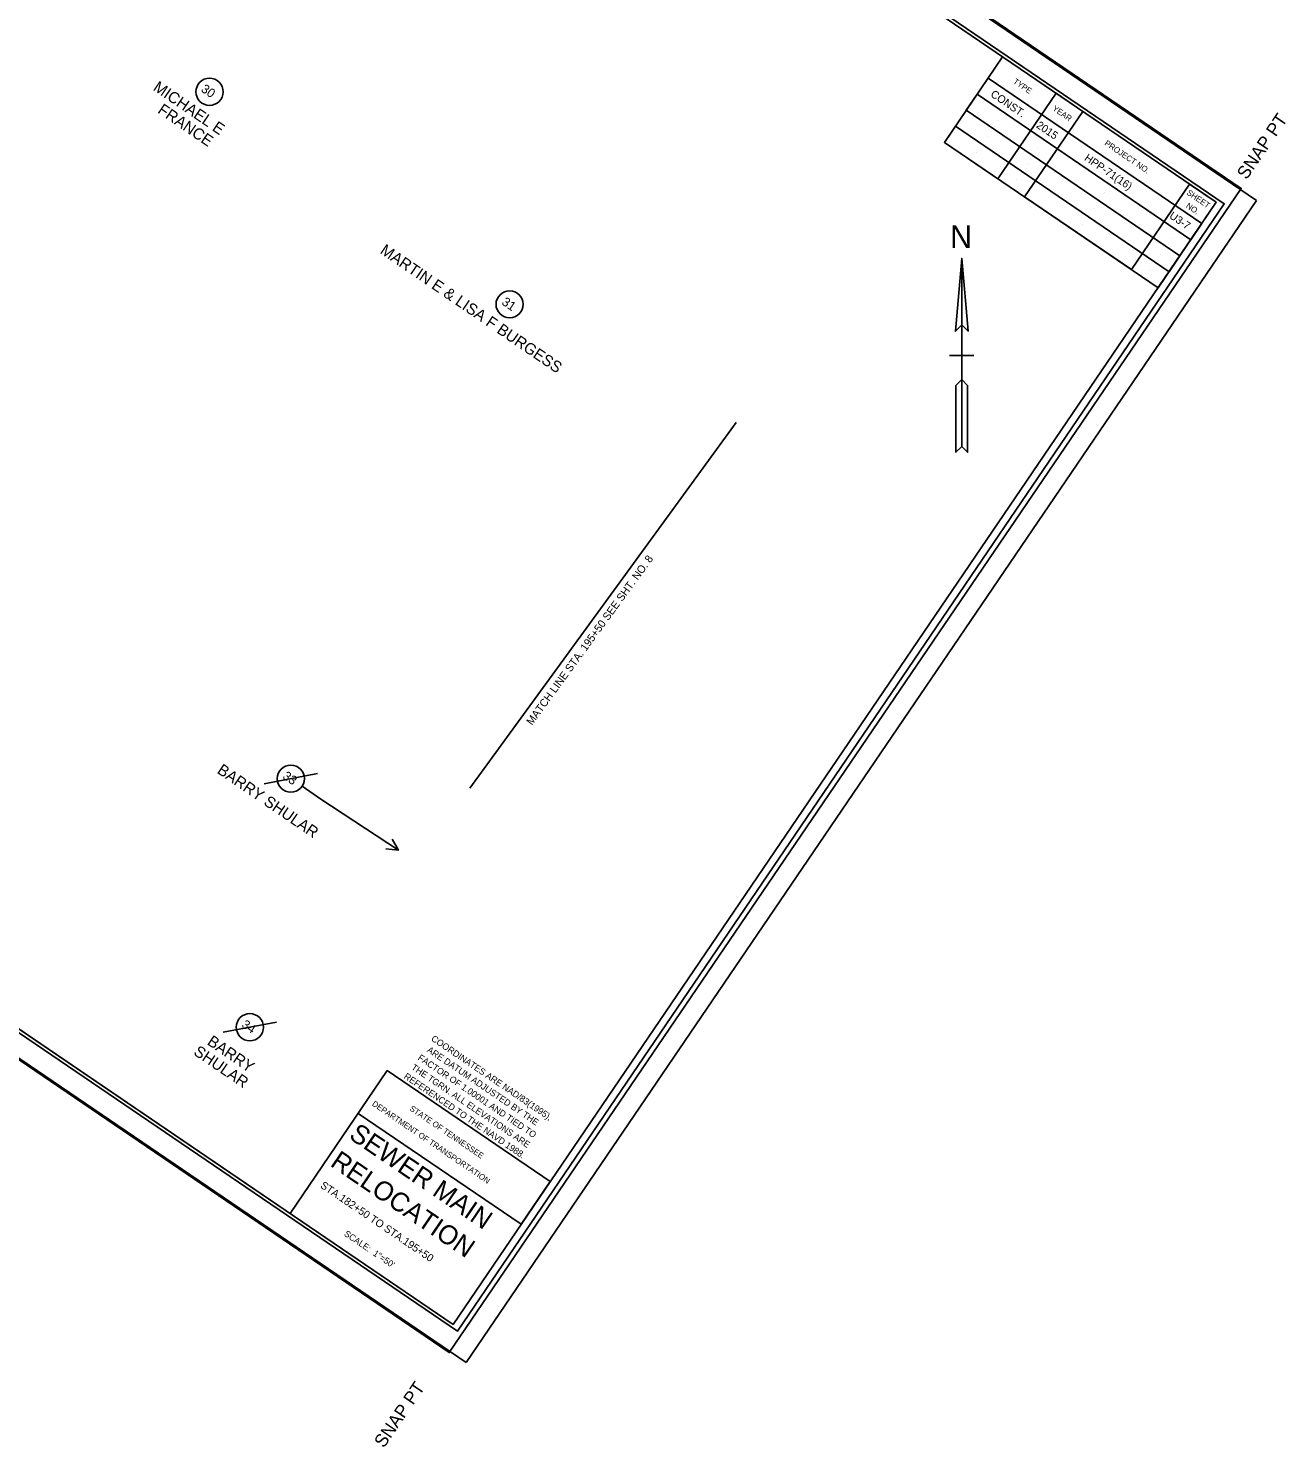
# Model space of a CAD drawing. Extents: x 2629906 to 2632029, y 567681 to 569670.
# Drawn here: x 2631056 to 2632029, y 567681 to 568779 of the extents above; entities that cross this region are included whole.
import ezdxf

# ---------------------------------------------------------------- set-up
doc = ezdxf.new("R2010")
doc.units = 0
for name, color, linetype in [('DESIGN - CENTERLINE - Proposed Text', 7, 'Continuous'), ('DESIGN - SCRATCH - User 1', 7, 'Continuous'), ('DESIGN - SHEET - Corner Text', 7, 'Continuous'), ('DESIGN - SHEET - Light Grid', 7, 'Continuous'), ('DESIGN - SHEET - Linework', 7, 'Continuous'), ('DESIGN - SHEET - Plot Shape', 7, 'Continuous'), ('SURVEY - PROPERTY - Owners', 7, 'Continuous'), ('SURVEY - PROPERTY - Tract Numbers', 7, 'Continuous')]:
    doc.layers.add(name, color=color, linetype=linetype)

msp = doc.modelspace()

# ---------------------------------------------------------------- linework, layer by layer
at = {"layer": 'DESIGN - CENTERLINE - Proposed Text'}
for p, q in [((2631778.1, 568525.9), (2631768.7, 568525.9)), ((2631787.6, 568525.9), (2631778.1, 568525.9))]:
    msp.add_line(p, q, dxfattribs=at)
for points in [[(2631778.1, 568600.9), (2631773.2, 568544.6), (2631778.1, 568549.5), (2631783, 568544.6), (2631778.1, 568600.9), (2631778.1, 568455.4), (2631782.7, 568450.9), (2631782.7, 568502.6), (2631778.1, 568507.2), (2631773.6, 568502.6), (2631773.6, 568450.9), (2631778.1, 568455.4)], [(2631397.5, 568191.1), (2631500.6, 568332.6), (2631603.6, 568474)]]:
    msp.add_lwpolyline(points, dxfattribs=at)
for points in [[(2631778.1, 568549.5), (2631783, 568544.6), (2631778.1, 568600.9)], [(2631773.6, 568450.9), (2631778.1, 568455.4), (2631778.1, 568507.2), (2631773.6, 568502.6)]]:
    msp.add_lwpolyline(points, close=True, dxfattribs=at)
at = {"layer": 'DESIGN - SCRATCH - User 1'}
for p, q in [((2631815, 568720.1), (2631815, 568720.1)), ((2631806.5, 568707.7), (2631806.5, 568707.7)), ((2631845.6, 568699.2), (2631845.6, 568699.2)), ((2631798.1, 568695.2), (2631798.1, 568695.2)), ((2631837.1, 568686.8), (2631837.1, 568686.8)), ((2631789.7, 568682.8), (2631789.7, 568682.8)), ((2631828.7, 568674.4), (2631828.7, 568674.4)), ((2631897.2, 568664.1), (2631897.2, 568664.1)), ((2631820.3, 568662), (2631820.3, 568662)), ((2631888.8, 568651.7), (2631888.8, 568651.7)), ((2631880.4, 568639.3), (2631880.4, 568639.3)), ((2631871.9, 568626.9), (2631871.9, 568626.9)), ((2631948.9, 568628.9), (2631948.9, 568628.9)), ((2631940.5, 568616.5), (2631940.5, 568616.5)), ((2631932, 568604.1), (2631932, 568604.1)), ((2631923.6, 568591.7), (2631923.6, 568591.7)), ((2631494.5, 568336.4), (2631494.5, 568336.4)), ((2631347.8, 567857.8), (2631347.8, 567857.8))]:
    msp.add_line(p, q, dxfattribs=at)
at = {"layer": 'DESIGN - SHEET - Light Grid'}
msp.add_lwpolyline([(2630011.2, 568707.4), (2631387.9, 567770.9), (2631981.3, 568643.2), (2630604.6, 569579.7)], close=True, dxfattribs=at)
at = {"layer": 'DESIGN - SHEET - Linework'}
for p, q in [((2630518, 569658.2), (2632006.3, 568645.8)), ((2629906.4, 568759.1), (2631394.7, 567746.7)), ((2632006.3, 568645.8), (2631394.7, 567746.7))]:
    msp.add_line(p, q, dxfattribs=at)
for points in [[(2630673.6, 569529.8), (2630083, 568661.6), (2631384.6, 567776.2), (2631975.1, 568644.4), (2630673.6, 569529.8)], [(2631809.8, 568756.9), (2631764.8, 568690.7), (2631930.1, 568578.2), (2631975.1, 568644.4), (2631954.5, 568658.4), (2631909.5, 568592.3), (2631826.8, 568648.5), (2631871.8, 568714.7), (2631851.1, 568728.7), (2631806.1, 568662.6), (2631764.8, 568690.7), (2631773.2, 568703.1), (2631938.6, 568590.6), (2631947, 568603), (2631781.6, 568715.5), (2631790.1, 568727.9), (2631955.5, 568615.4), (2631963.9, 568627.8), (2631798.5, 568740.3)], [(2631258.5, 567862), (2631333.6, 567972.5), (2631459.7, 567886.7), (2631437.2, 567853.6), (2631311.1, 567939.4)]]:
    msp.add_lwpolyline(points, dxfattribs=at)
at = {"layer": 'DESIGN - SHEET - Plot Shape'}
for points in [[(2630588.8, 569611.3), (2631994.4, 568655.1), (2631381.6, 567754.4), (2629976, 568710.6)], [(2630603.2, 569577.6), (2631975.1, 568644.4), (2631384.6, 567776.2), (2630012.6, 568709.5)]]:
    msp.add_lwpolyline(points, close=True, dxfattribs=at)
at = {"layer": 'SURVEY - PROPERTY - Tract Numbers'}
for p, q in [((2631238.4, 568194.5), (2631279.6, 568202.3)), ((2631206.6, 568002.2), (2631247.9, 568010.1))]:
    msp.add_line(p, q, dxfattribs=at)
for points in [[(2631282.2, 568182.6), (2631267.7, 568192.5)], [(2631342.3, 568143.1), (2631282.2, 568182.6)], [(2631337.4, 568151.5), (2631342.3, 568143.1), (2631332.6, 568144.2)]]:
    msp.add_lwpolyline(points, dxfattribs=at)
for centre in [(2631196.1, 568729.8), (2631428.3, 568565.4), (2631259, 568198.4), (2631227.3, 568006.1)]:
    msp.add_circle(centre, 10.5, dxfattribs=at)

# ---------------------------------------------------------------- texts
at = {"layer": 'DESIGN - CENTERLINE - Proposed Text'}
msp.add_text('N', height=17.7, dxfattribs=at).set_placement((2631769.1, 568608.9))
msp.add_text('MATCH LINE STA. 195+50 SEE SHT. NO. 8', height=6, rotation=53.918, dxfattribs=at).set_placement((2631445.6, 568239.3))
at = {"layer": 'DESIGN - SHEET - Corner Text'}
for s, height, rotation, p in [('TYPE', 4.5, 325.7738, (2631817.5, 568736.8)), ('CONST.', 6, 325.7738, (2631799.9, 568726.7)), ('YEAR', 4.5, 325.7738, (2631847.9, 568715.9)), ('  SNAP PT', 10, 55.7738, (2631994.4, 568655.1)), ('2015', 6, 325.7738, (2631835.3, 568702.6)), ('PROJECT NO.', 4.5, 325.7738, (2631888.2, 568689)), ('HPP-71(16)', 6, 325.7738, (2631872.5, 568677.3)), ('SHEET', 4.5, 325.7738, (2631951.8, 568650.7)), ('NO.', 4.5, 325.7738, (2631951.2, 568640.6)), ('U3-7', 6, 325.7738, (2631938.2, 568632.6)), ('COORDINATES ARE NAD/83(1995),', 5, 325.7738, (2631367.1, 567996.1)), ('FACTOR OF 1.00001 AND TIED TO', 5, 325.7738, (2631356.8, 567981.3)), ('ARE DATUM ADJUSTED BY THE', 5, 325.7738, (2631363.9, 567987.4)), ('THE TGRN. ALL ELEVATIONS ARE', 5, 325.7738, (2631351.7, 567973.9)), ('REFERENCED TO THE NAVD 1988.', 5, 325.7738, (2631346, 567966.9)), ('DEPARTMENT OF TRANSPORTATION', 4.5, 325.7738, (2631321.4, 567945.8)), ('STATE OF TENNESSEE', 4.5, 325.7738, (2631350.5, 567942.1)), ('SEWER MAIN', 14.76, 325.7738, (2631303.2, 567920.5)), ('RELOCATION', 14.76, 325.7738, (2631288.7, 567899.2)), ('STA.182+50 TO STA.195+50', 5.905, 325.7738, (2631281.3, 567882.4)), ('SCALE:  1"=50\'', 4.921, 325.7738, (2631299.7, 567845.2)), ('SNAP PT  ', 10, 55.7738, (2631331, 567680))]:
    msp.add_text(s, height=height, rotation=rotation, dxfattribs=at).set_placement(p)
at = {"layer": 'SURVEY - PROPERTY - Owners'}
for s, p in [('MICHAEL E', (2631151.8, 568731.5)), ('FRANCE', (2631155.3, 568714)), ('MARTIN E & LISA F BURGESS', (2631327.4, 568605.3)), ('BARRY SHULAR', (2631201.3, 568203.2)), ('BARRY', (2631193.6, 567993.2)), ('SHULAR', (2631183.1, 567985.3))]:
    msp.add_text(s, height=8.75, rotation=325.7738, dxfattribs=at).set_placement(p)
at = {"layer": 'SURVEY - PROPERTY - Tract Numbers'}
for s, p in [('30', (2631188.9, 568730.5)), ('31', (2631421.6, 568565.7)), ('33', (2631252.1, 568198.9)), ('34', (2631220.3, 568006.6))]:
    msp.add_text(s, height=7, rotation=325.7738, dxfattribs=at).set_placement(p)

doc.saveas('drawing.dxf')
